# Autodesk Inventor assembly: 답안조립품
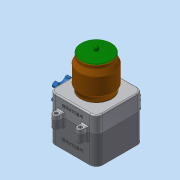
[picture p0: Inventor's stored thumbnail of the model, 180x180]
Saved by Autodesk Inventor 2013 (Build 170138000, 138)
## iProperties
Created: 2018-01
Part Number: 답안조립품
Document SubType Name: Assembly
Designer: Administrator
Author: Administrator
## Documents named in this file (9)
- C:\Users\Administrator\Desktop\480108V1028\답안조립품.iam
- C:\Users\Administrator\Desktop\480108V1028\본체.ipt
- C:\Users\Administrator\Desktop\480108V1028\본체커버.ipt
- C:\Users\Administrator\Desktop\480108V1028\핸들.ipt
- C:\Users\Administrator\Desktop\480108V1028\핸들축.ipt
- C:\Users\Administrator\Desktop\480108V1028\용기.ipt
- C:\Users\Administrator\Desktop\480108V1028\용기캡.ipt
- C:\Users\Administrator\Desktop\480108V1028\볼트 M3x12.ipt
- C:\Users\Administrator\Desktop\480108V1028\볼트 M4x12.ipt
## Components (2 placed, 2 different names)
1. 핸들:1
2. 핸들축:1
